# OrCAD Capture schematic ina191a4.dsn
size A
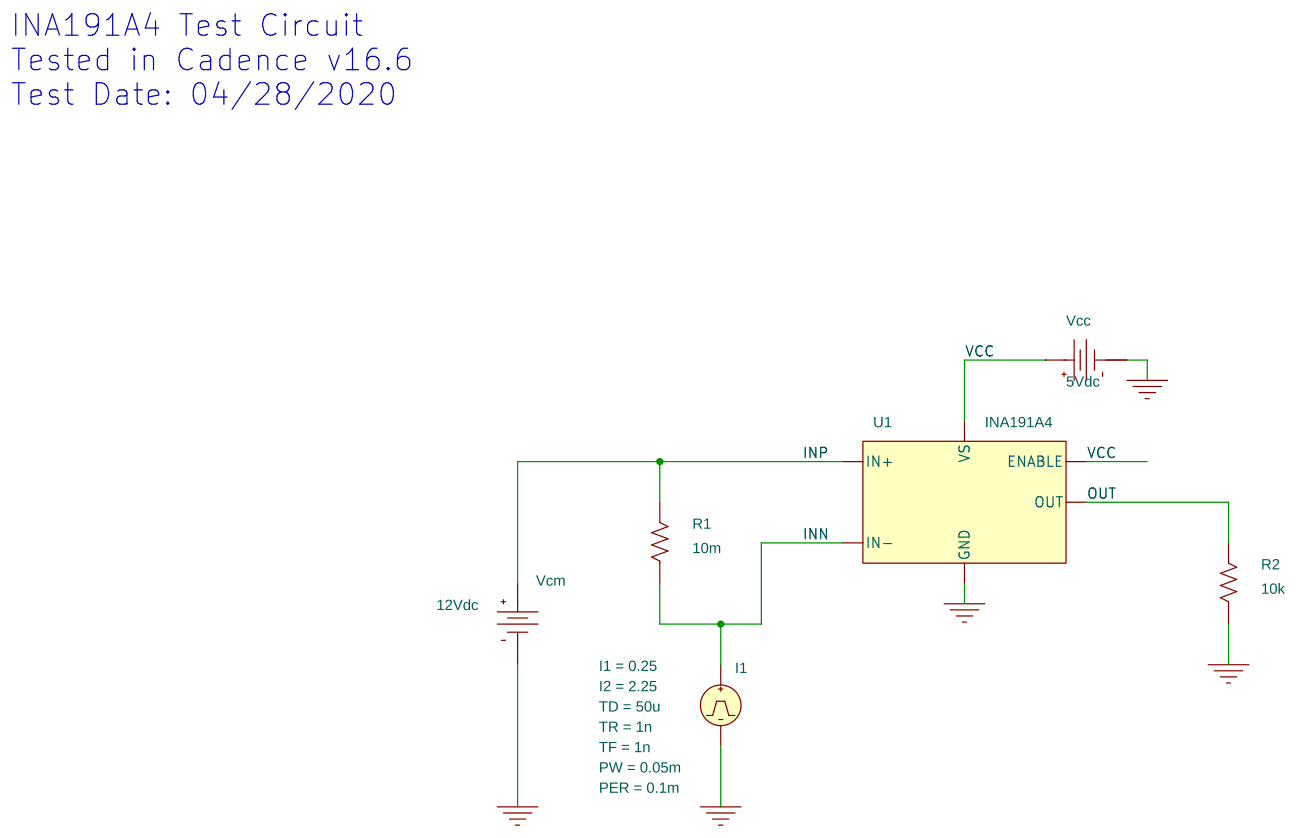
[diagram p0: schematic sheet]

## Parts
I1  IPULSE
R1  10m  [AX/RC05]
R2  10k  [AX/RC05]
U1  INA191A4
Vcc  VDC
Vcm  VDC

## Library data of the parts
I1 = IPULSE: I1: 0.25; I2: 2.25; PER: 0.1m; PW: 0.05m; TD: 50u; TF: 1n; TR: 1n
R1 R2 = R
U1 = INA191A4
Vcc = VDC: DC: 5Vdc
Vcm = VDC: DC: 12Vdc

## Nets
VCC: U1.ENABLE U1.VS Vcc.0(+)
0: I1.2(-) R2.1 U1.GND Vcc.1(-) Vcm.1(-)
INN: I1.1(+) R1.1 U1.IN-
INP: R1.2 U1.IN+ Vcm.0(+)
OUT: R2.2 U1.OUT

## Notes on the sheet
- INA191A4 Test Circuit
  Tested in Cadence v16.6
  Test Date: 04/28/2020
